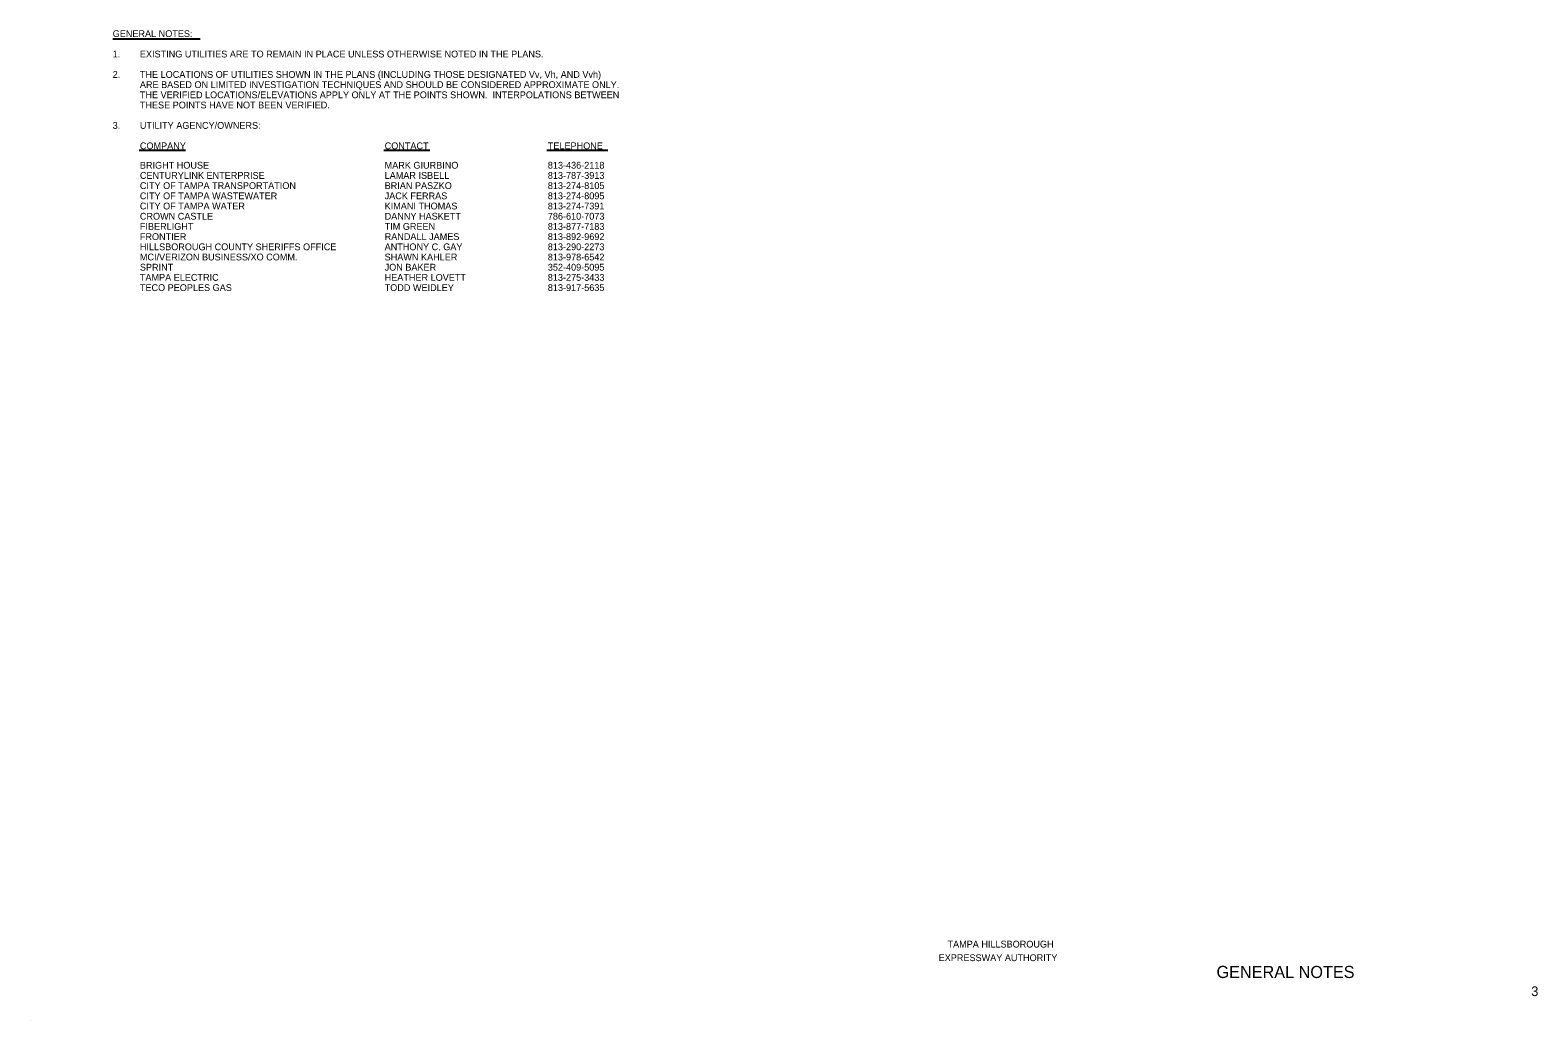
# Model space of a CAD drawing. Extents: x -820.7 to -805.2, y -2198.1 to -2187.9.
import ezdxf

# ---------------------------------------------------------------- set-up
doc = ezdxf.new("R2010")
doc.units = 0
for name, color, linetype in [('AdhocPoint_dp', 7, 'Continuous'), ('Default', 7, 'Continuous'), ('TextLabel', 7, 'Continuous'), ('TextMisc', 7, 'Continuous'), ('TextShtNo', 7, 'Continuous')]:
    doc.layers.add(name, color=color, linetype=linetype)

msp = doc.modelspace()

# ---------------------------------------------------------------- linework, layer by layer
at = {"layer": 'AdhocPoint_dp'}
msp.add_line((-820.678, -2198.145), (-820.678, -2198.145), dxfattribs=at)
at = {"layer": 'TextLabel'}
for p, q in [((-819.828, -2188.035), (-818.928, -2188.035)), ((-819.555, -2189.18), (-819.078, -2189.18)), ((-817.035, -2189.18), (-816.563, -2189.18)), ((-815.358, -2189.18), (-814.73, -2189.18))]:
    msp.add_line(p, q, dxfattribs=at)

# ---------------------------------------------------------------- texts
at = {"layer": 'Default'}
for s, p in [('BRIGHT HOUSE', (-819.548, -2189.37)), ('MARK GIURBINO', (-817.028, -2189.37)), ('813-436-2118', (-815.348, -2189.37)), ('CENTURYLINK ENTERPRISE', (-819.548, -2189.475)), ('LAMAR ISBELL', (-817.028, -2189.475)), ('813-787-3913', (-815.348, -2189.475)), ('CITY OF TAMPA TRANSPORTATION', (-819.548, -2189.58)), ('CITY OF TAMPA WASTEWATER', (-819.548, -2189.685)), ('JACK FERRAS', (-817.028, -2189.685)), ('BRIAN PASZKO', (-817.028, -2189.58)), ('813-274-8105', (-815.348, -2189.58)), ('813-274-8095', (-815.348, -2189.685)), ('CITY OF TAMPA WATER', (-819.548, -2189.79)), ('KIMANI THOMAS', (-817.028, -2189.79)), ('813-274-7391', (-815.348, -2189.79)), ('CROWN CASTLE', (-819.548, -2189.895)), ('FIBERLIGHT', (-819.548, -2190)), ('TIM GREEN', (-817.028, -2190)), ('DANNY HASKETT', (-817.028, -2189.895)), ('813-877-7183', (-815.348, -2190)), ('786-610-7073', (-815.348, -2189.895)), ('FRONTIER', (-819.548, -2190.105)), ('RANDALL JAMES', (-817.028, -2190.105)), ('813-892-9692', (-815.348, -2190.105)), ('HILLSBOROUGH COUNTY SHERIFFS OFFICE', (-819.548, -2190.21)), ('MCI/VERIZON BUSINESS/XO COMM.', (-819.548, -2190.315)), ('ANTHONY C. GAY', (-817.028, -2190.21)), ('SHAWN KAHLER', (-817.028, -2190.315)), ('813-290-2273', (-815.348, -2190.21)), ('813-978-6542', (-815.348, -2190.315)), ('SPRINT', (-819.548, -2190.42)), ('JON BAKER', (-817.028, -2190.42)), ('352-409-5095', (-815.348, -2190.42)), ('TAMPA ELECTRIC', (-819.548, -2190.525)), ('HEATHER LOVETT', (-817.028, -2190.525)), ('813-275-3433', (-815.348, -2190.525)), ('TECO PEOPLES GAS', (-819.548, -2190.63)), ('TODD WEIDLEY', (-817.028, -2190.63)), ('813-917-5635', (-815.348, -2190.63)), ('TAMPA HILLSBOROUGH', (-811.233, -2197.39)), ('EXPRESSWAY AUTHORITY', (-811.324, -2197.53))]:
    msp.add_text(s, height=0.07, dxfattribs=at).set_placement(p)
at = {"layer": 'TextLabel'}
for s, p in [('GENERAL NOTES:', (-819.828, -2188.015)), ('1.', (-819.828, -2188.225)), ('EXISTING UTILITIES ARE TO REMAIN IN PLACE UNLESS OTHERWISE NOTED IN THE PLANS.', (-819.548, -2188.225)), ('2.', (-819.828, -2188.435)), ('THE LOCATIONS OF UTILITIES SHOWN IN THE PLANS (INCLUDING THOSE DESIGNATED Vv, Vh, AND Vvh)', (-819.548, -2188.435)), ('ARE BASED ON LIMITED INVESTIGATION TECHNIQUES AND SHOULD BE CONSIDERED APPROXIMATE ONLY.', (-819.548, -2188.54)), ('THE VERIFIED LOCATIONS/ELEVATIONS APPLY ONLY AT THE POINTS SHOWN.  INTERPOLATIONS BETWEEN ', (-819.548, -2188.645)), ('THESE POINTS HAVE NOT BEEN VERIFIED.', (-819.548, -2188.75)), ('3.', (-819.828, -2188.96)), ('UTILITY AGENCY/OWNERS:', (-819.548, -2188.96)), ('COMPANY', (-819.548, -2189.17)), ('CONTACT', (-817.028, -2189.17)), ('TELEPHONE', (-815.348, -2189.17))]:
    msp.add_text(s, height=0.07, dxfattribs=at).set_placement(p)
at = {"layer": 'TextMisc'}
msp.add_text('        GENERAL NOTES          ', height=0.125, dxfattribs=at).set_placement((-808.835, -2197.704))
at = {"layer": 'TextShtNo'}
msp.add_text('  3   ', height=0.1, dxfattribs=at).set_placement((-805.298, -2197.89))

doc.saveas('drawing.dxf')
